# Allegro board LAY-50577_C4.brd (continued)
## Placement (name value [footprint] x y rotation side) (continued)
U5  UM1750S-00  [SOT23-5_A]  138.54 93.68 180 top
U6  MIMXRT1189CVM8C  [BGA289_0P8_14X14_1P52MM]  100.69 70.44 0 top
U10  W25Q128JWSIQ  [SO8-25X75-200]  149.59 65.86 90 bottom
U11  MT35XU512ABA2G12-0AAT  [PBGA24_1_6X8MM]  105.52 113.24 90 top
U12  W25Q128JWSIQ  [SO8-25X75-200]  105.91 122.51 270 bottom
U13  MX25L4006EM2R-12G  [SO8-25X75-200]  74.28 92.41 270 top
U14  W9825G6KH  [TSOPII_54]  60.05 77.68 270 top
U15  W956A8MBYA5K  [PBGA24_1_6X8MM]  83.42 83.01 270 top
U16  W9825G6KH  [TSOPII_54]  60.05 53.67 270 top
U22  NC7WV04L6X  [MICROPAK_6P]  132.06 21.16 90 top
U23  NL17SZ126DF  [SC-70]  145.52 20.65 270 top
U25  SRV05-4  [SOT23_S6]  52.3 21.12 0 bottom
U26  IP4292CZ10-TBR  [XSON10_0P5_1P1X2P6MM]  128.25 119.46 270 top
U27  RTL8211FDI-CG  [QFN40_0P4_5X5MM]  126.6 112.85 270 top
U28  IP4292CZ10-TBR  [XSON10_0P5_1P1X2P6MM]  124.44 119.46 270 top
U29  RTL8211FDI-CG  [QFN40_0P4_5X5MM]  26.9 59.13 0 top
U30  IP4292CZ10-TBR  [XSON10_0P5_1P1X2P6MM]  20.3 60.78 0 top
U31  IP4292CZ10-TBR  [XSON10_0P5_1P1X2P6MM]  20.3 56.97 0 top
U32  IP4292CZ10-TBR  [XSON10_0P5_1P1X2P6MM]  22.33 86.06 0 top
U33  IP4292CZ10-TBR  [XSON10_0P5_1P1X2P6MM]  22.33 82.25 0 top
U34  RTL8211FDI-CG  [QFN40_0P4_5X5MM]  28.94 84.41 0 top
U37  NX5P3090UK  [WLCSP12_0P4_1P38X1P68MM_SMDP]  184.64 56.97 90 top
U38  RClamp0854P.TCT  [SLP1616P6]  187.05 61.8 90 top
U39  NX5P3090UK  [WLCSP12_0P4_1P38X1P68MM_SMDP]  187.56 73.36 90 top
U40  RClamp0854P.TCT  [SLP1616P6]  187.05 80.72 90 top
U41  TJA1057GT/3  [SO8_1P27_4X5]  73.26 101.12 0 top
U42  TJA1057GT/3  [SO8_1P27_4X5]  73.26 106.84 0 top
U43  74AVC8T245PW  [TSSOP24_65MM]  164.32 100.28 90 top
U44  74AVC8T245PW  [TSSOP24_65MM]  155.56 100.28 270 top
U45  AMC1106M05DWV  [SOIC8_1P27_7P6X5P95MM]  163.43 33.1 180 top
U46  LSM6DSOXTR  [LGA14_0P5_3X2P5]  169.02 22.43 270 top
U48  24LC32A  [TSSOP8]  161.02 22.94 90 top
U51  PRTR5V0U2X  [SOT143B]  8.11 116.16 270 top
U52  NX5P3090UK  [WLCSP12_0P4_1P38X1P68MM_SMDP]  11.49 99.52 270 top
U55  LPC55S69JEV98  [BGA98_0P5_7X7]  27.54 116.16 270 top
U56  74LVC1T45GW,125  [SOT-363_0P65_SMT]  31.86 98 0 top
U57  74LVC1T45GW,125  [SOT-363_0P65_SMT]  31.86 101.55 0 top
U58  SN74LVC2T45  [SSOP8_DCU]  41 107.9 270 top
U59  74LVC1T45GW,125  [SOT-363_0P65_SMT]  31.86 104.98 180 top
U60  NX3DV2567GU  [PQFN16_0P4_2P65X1P85]  42.53 97.49 180 top
U61  74AVC4TD245BQ  [DHVQFN16_0P5_3P6X2P6]  40.37 114.63 180 top
U62  XC6206P332PR  [SOT89_123_A]  12.68 109.17 0 top
U63  TMUX136MRSER  [UQFN10_0P5_2P05X1P55]  145.14 117.17 180 top
U64  TMUX136MRSER  [UQFN10_0P5_2P05X1P55]  148.95 117.17 180 top
U65  TMUX136MRSER  [UQFN10_0P5_2P05X1P55]  140.95 117.17 180 top
U66  TMUX136MRSER  [UQFN10_0P5_2P05X1P55]  144.89 72.72 90 top
U67  TMUX136MRSER  [UQFN10_0P5_2P05X1P55]  149.84 72.72 90 top
U68  TMUX136MRSER  [UQFN10_0P5_2P05X1P55]  154.79 72.72 90 top
U69  TMUX136MRSER  [UQFN10_0P5_2P05X1P55]  101.71 105.62 0 top
U70  TMUX136MRSER  [UQFN10_0P5_2P05X1P55]  110.98 105.62 0 top
U71  TMUX136MRSER  [UQFN10_0P5_2P05X1P55]  106.03 105.62 0 top
U72  FT232RQ  [QFN32_MC1320X]  53.83 126.95 180 top
U73  SN74LVC2G126  [SSOP8]  56.24 121.24 0 top
U74  RClamp0854P.TCT  [SLP1616P6]  53.52 132.67 180 top
U96  TMUX136MRSER  [UQFN10_0P5_2P05X1P55]  43.03 84.28 90 top
U97  TMUX136MRSER  [UQFN10_0P5_2P05X1P55]  43.03 80.6 90 top
U98  TMUX136MRSER  [UQFN10_0P5_2P05X1P55]  43.03 76.91 90 top
U99  TMUX136MRSER  [UQFN10_0P5_2P05X1P55]  43.03 73.23 90 top
U100  TMUX136MRSER  [UQFN10_0P5_2P05X1P55]  43.03 69.55 90 top
U101  TMUX136MRSER  [UQFN10_0P5_2P05X1P55]  43.03 65.86 90 top
U103  TMUX136MRSER  [UQFN10_0P5_2P05X1P55]  43.03 59.39 90 top
U106  TMUX136MRSER  [UQFN10_0P5_2P05X1P55]  43.03 55.45 90 top
U115  FXLS8974CFR3  [DFN_10_0P4_2X2]  60.31 92.66 180 top
U116  SPH0641LM4H-1  [MIC5_3P6X2P75MM]  155.13 51.94 0 bottom
U117  SPH0641LM4H-1  [MIC5_3P6X2P75MM]  190.63 88.22 0 bottom
U118  SPH0641LM4H-1  [MIC5_3P6X2P75MM]  119.63 88.22 0 bottom
U119  SPH0641LM4H-1  [MIC5_3P6X2P75MM]  155.13 124.5 0 bottom
U121  RTL8201FI-VC-CG  [QFN32_0P5_5X5_S142EP]  57.51 31.07 90 top
U123  RTL8201FI-VC-CG  [QFN32_0P5_5X5_S142EP]  89.26 31.07 90 top
U124  SRV05-4  [SOT23_S6]  75.16 21.12 0 bottom
U125  NTS0102  [TSSOP8_A]  115.04 106.63 270 top
U126  NTS0102  [TSSOP8_A]  63.86 104.73 90 top
U312  DMG1016V-7  [SOT-563_6P_0P5_SMT]  121.11 61.5 0 top
U356  UM803RS  [SOT-23]  102.34 38.94 180 top
U361  74LVC07APW  [TSSOP14]  36.05 40.46 0 top
U362  74LVC1G07GW-Q100  [SC70-5]  57.26 104.09 0 bottom
U365  74LVC1G07GW-Q100  [SC70-5]  53.45 104.09 0 bottom
U366  74LVC1G07GW-Q100  [SC70-5]  49.64 104.09 0 bottom
U369  WM8962BECSN/R  [BGA49_0P5_3P62X4]  89.26 118.7 90 top
U410  74LVC1G07GW-Q100  [SC70-5]  121.52 118.06 90 bottom
U416  74LVC1G07GW-Q100  [SC70-5]  130.03 104.73 90 bottom
U417  74LVC1G07GW-Q100  [SC70-5]  24.62 75.39 0 top
U418  74LVC1G07GW-Q100  [SC70-5]  39.1 87.45 270 top
X1  25MHz  [XTAL4_5P2X3P4MM_SM]  135.82 118.95 0 top
X2  25MHz  [XTAL4_5P2X3P4MM_SM]  24.87 68.79 0 top
X3  25MHz  [XTAL4_5P2X3P4MM_SM]  26.9 94.06 0 top
X4  25MHz  [XTAL4_5P2X3P4MM_SM]  47.22 27.51 270 top
X6  25MHz  [XTAL4_5P2X3P4MM_SM]  78.72 27.51 270 top
Y1  32.768KHZ  [XTAL2-3P2X1P5-SM]  103.99 54.31 0 top
Y2  24MHz  [XTL4_2P1X1P7MM_SM]  109.33 55.58 180 top
Y3  32.7680KHZ  [XTLOSC4_3P3X1P6_SM]  172.19 119.2 270 top
Y4  16 MHz  [XTLOSC4_2P6X2P1MM_SM]  19.79 118.21 270 top

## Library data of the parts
BH1 BH12 = MOUNT_HOLE
C1-C3 C5 C6 C8 C10-C15 C17-C36 C39 C42-C49 C51 C53-C58 C60 C62 C64-C66 C69-C71 C73-C93 C98-C126 C165 C167-C170 C180-C248 C263 C264 C267 C268 C270-C273 C275-C279 C281-C301 C303-C312 C317 C338 C346-C356 C358-C365 C370-C373 C385-C395 C397-C414 C431-C436 C452 C455 C462-C466 C468-C473 C475-C478 C481 C482 C509 C515 C516 C522-C528 C562 C563 C565 C567 C569 C571 C573 C577-C603 C887 C902 = CAP_NP
C4 C166 C274 C280 C326 = CAP_NP: tolerance: 20%
C7 C9 C59 C61 C63 C68 C72 C94 C479 C480 C507 C508 C510 C517-C521 C529 C530 C574-C576 C604 C903 C908-C910 = F1202
C37 C38 C95 C96 C176-C179 C323 C324 C511-C514 = CAP_NP: tolerance: 5%
D1 = ZDIODE
D2 D4 D5 D8 D9 D25-D27 D41-D43 = DIODE_SCHTKY
D3 D37 = LED_DUAL_SEP_RG
D6 D7 D23 D24 D29-D33 D35 D39 = LED
D10-D20 = DIODE_TVS
D21 D22 = DIODE_NUP2105L
D28 = BAV99DW
D46 TVS1 = DIODE_TVS_BIDIR
F1 = FUSE
FL1 FL2 = FILTER_4P
H1-H6 = SPACER
J1 J51 = CONN_HDR_4X2
J2 = PHONEJACK-3
J3-J7 J9 J10 J12 J14 J23 J25 J26 J46 J49 J77-J81 J88-J100 J102-J105 J135 JP2-JP7 = CONN_HDR_2X1
J8 = HDR-1X12
J11 J34 J35 J57-J59 J63 J65 J72 J73 J75 J76 = CONN_HDR_3X1
J15 = CON8_SDCARD_DETECT
J24 J27 = KLPX0848A
J28 J32 = RJ45_7499211121A
J29-J31 = RJ45_2 DUAL_LED_10P
J33 J53 J60 J68 = MICRO_USB_CONN_9PIN
J36 = CON_67_FEMALE_RA
J37 J44 J69 = CONN_HDR_10X2
J39 J45 = CONN_HDR_8X2
J41 J67 = CONN_HDR_6X2
J47 = CONN_HDR_12X2
J48 J56 = CONN_HDR_5X2
J50 = CONN_HDR_4X1
J62 J70 = CONN_HDR_8X1
J71 = QSE_014_DP
J101 = 3.5MM_AUDIO_JACK
J108 = CONN_HDR_5X1
J134 = QSH030
JP1 = JUMPER1x2
L1 = IND: tolerance: 30%
L2-L4 L6-L9 L22 L33 L34 L36-L38 = INDUCTOR_FERRITE
L5 L15 L18 L23 L25 = INDUCTOR
L16 L19 L21 = DLW43
L24 = BEAD
L29 = IND_FERRITE
P2 = MIC_POM
Q1 Q2 = FDMA530PZ
Q3 = PNP
Q4 = NMOS_2N7002BKW_3P
Q5 Q11 Q12 = 2SK3018
Q6 = MOSFET_P
Q7 Q8 Q19-Q21 Q23 = NPN
Q15 = NMOS_3P_A
R1 R2 R6 R7 R12-R25 R27 R28 R30-R45 R47 R51-R59 R62 R71 R74 R76 R79-R89 R92-R116 R118 R120 R122 R124-R144 R146 R148 R149 R186-R188 R224-R227 R257 R260 R264 R266 R280 R283-R285 R291-R293 R295 R297-R299 R303 R308 R312-R320 R331 R336 R338 R339 R341 R343 R344 R348 R350 R376 R381 R382 R396 R397 R404 R405 R428-R457 R464 R466-R468 R470 R472-R477 R479-R481 R492-R510 R517 R519-R521 R523-R532 R543-R545 R547-R552 R554-R563 R570 R572-R574 R576 R622 R623 R625 R626 R628-R634 R636-R638 R640-R644 R646 R647 R649-R653 R655 R656 R658-R661 R663 R664 R669 R675-R692 R694 R696 R697 R699 R701 R703 R705-R738 R746-R753 R755-R785 R798 R800 R801 R803-R806 R808 R809 R811 R814-R818 R829-R842 R844 R845 R848 R849 R851 R853 R854 R861-R887 R891-R893 R898-R904 R958 R964 R1018 R1021-R1036 R1038-R1049 R1051-R1059 R1061-R1069 R1071-R1073 R1076-R1081 R1083-R1090 R1094-R1097 R1099 R1100 R1102-R1109 R1112 R1113 R1116-R1119 R1170-R1181 R1190-R1192 R1231 R1232 R1236 R1271 R1273 R1274 R1279 R1280 R1282-R1288 R1304-R1307 R1312-R1316 R1319-R1328 R1330-R1334 R1338-R1340 R1342-R1344 R1900 R2090 R2098-R2104 R2113 R2134-R2161 R2166 R2168 R2169 R2579 R2584-R2587 R2592 R2593 R2596 R2597 R2615 R2635 R2639-R2644 R2694 R2697 = RES
R3-R5 R8-R11 R64 R65 R256 R259 R270 R287-R290 R294 R335 R375 R378 R408 R465 R518 R571 R624 R627 R635 R639 R648 R657 R662 R665 R821-R828 R846 R847 R850 R852 R897 R1074 R1075 R1091 R1093 R1281 R2107 R2109 R2111 R2684 R2696 = RES: tolerance: 5%
R26 R377 R379 R380 R391-R393 R395 R469 R522 R575 R666 R667 R1275-R1278 R2695 = RES: tolerance: 1%
R29 R117 R119 R121 R123 R258 R296 R668 R670-R674 R2594 R2595 R2603-R2614 R2620 = RES: signal model: RES_0402_CC_DISCRETE_0.45_MM_470-75394_0_0
R151-R185 R189-R196 R198 R200-R223 R228-R235 R238 R240 R242 R244 R246 R248 R250 R252 R327 R332 R333 R337 R959 R960 R1122 R1169 R1229 R1230 R1233-R1235 R1237-R1240 R1259-R1270 R1272 R1289-R1303 R1308-R1311 R1329 R2114-R2133 = RES: signal model: RES_0402_CC_DISCRETE_0.45_MM_47_0
R271-R277 R2576 R2616-R2619 = RES: signal model: RES_RC0402_25_DISCRETE_0.4_MM_470-82894_0_0
R458-R463 R511-R516 R564-R569 = RES: tolerance: 5%; signal model: RES_0402_CC_DISCRETE_0.45_MM__1_0
R812 R813 = RES: signal model: RES_0402_CC_DISCRETE_0.41MM_470-75634_33_33
SW1 = SW_DPDT_3
SW2-SW4 SW7 SW8 = EDGE_MOUNT_PB_SW_2
SW5 = SW_DIP4
SW6 = SW2P_SPST
T1 T2 = XFMR: room: SPDIF
TP1 TP2 TP7-TP18 TP24-TP26 TP41 TP53-TP66 TP77 TP78 TP94-TP101 TP1022-TP1031 TP1065-TP1071 = T POINT R: Tolerance: TOLERANCE; User Part Number: 510-75618
TP3-TP6 = TEST_POINT
TP42-TP44 = TESTLOOP
TP45-TP48 TP51 TP67-TP76 TP102 TP103 TP1055-TP1064 = TestLoop
TP50 = TEST POINT L
U1 = MP2144GJ_TSOT23_8P
U2 = UM805_4P
U3 U5 = UM1750S-00_5P
U4 = LM1117_FXD
U6 = RT1180-BGA289
U10 U12 = 25WP_8P
U11 = MT35X_TBGA24
U13 = MX25L6406EM2I_SOP8
U14 U16 = W9825G6KH_54P
U15 = W959D8NFYA5_TFBGA24
U22 = 74AUP2G06GW
U23 = 100201_SO-1
U25 U124 = SRV05-4
U26 U28 U30-U33 = PUSB3F96_DFN2510A_10P
U27 U29 U34 = RTL8211FD-40P
U37 U39 U52 = NX5P3090UK_WLCSP12
U38 U40 U74 = RCLAMP1654P_NEW
U41 U42 = TJA1057GT3_8P
U43 U44 = SN74AVC8T245
U45 = AMC1106_SOIC8P
U46 = LSM6DSO_LGA14P
U48 = Atmel_Serial_EEPROM_64K-1
U51 = PRTR5V0U2X: signal model: PRTR5V0U2X_SOT143B_IC_1.1MM_315_PRTR5V0U2X
U55 = NIOBE4_MINI_FBGA98
U56 U57 U59 = 74LVCH1T45_6P
U58 = SN74LVC2T45DCUT_8P
U60 = NX3DV2567GU_XQFN_16P
U61 = 74AVC4TD245BQ_DHVQFN16
U62 = S0T89_3P
U63-U71 U96-U101 U103 U106 = TMUX136_UQFN10
U72 = FT232RQ
U73 = SN74LVC2G126DCTR
U115 = FXLS8962AF_DFN10
U116-U119 = MIC_SPH0641LM4H-1_5P
U121 = RTL8201FI: signal model: RES_0402_CC_DISCRETE_0.45_MM_47_0
U123 = RTL8201FI
U125 U126 = NTB0102_8P
U312 = NX3008_SOT666_6PIN
U356 = SGM803_SOT23-3P
U361 = 74LVC07APW
U362 U365 U366 U410 U416-U418 = 74AUP1G07GW
U369 = WM8962_BGA_49P_CUST
X1-X4 X6 Y2 Y4 = XTAL_13
Y1 = CRYSTAL
Y3 = OSC_4P

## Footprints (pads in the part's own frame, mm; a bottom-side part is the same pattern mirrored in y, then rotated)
100MIL_TH
  rect 1.422x1.422 hole 0.914: 1(0,0)
  round 1.422 hole 0.914: 2(2.54,0)
0402_CC
  rect 0.457x0.508 smd: 1(-0.375,0) 2(0.375,0)
BGA49_0P5_3P62X4
  round 0.254 smd: A1(-1.5,1.5) A2(-1,1.5) A3(-0.5,1.5) A4(0,1.5) A5(0.5,1.5) A6(1,1.5) A7(1.5,1.5) B1(-1.5,1) B2(-1,1) B3(-0.5,1) B4(0,1) B5(0.5,1) B6(1,1) B7(1.5,1) C1(-1.5,0.5) C2(-1,0.5) C3(-0.5,0.5) C4(0,0.5) C5(0.5,0.5) C6(1,0.5) C7(1.5,0.5) D1(-1.5,0) D2(-1,0) D3(-0.5,0) D4(0,0) D5(0.5,0) D6(1,0) D7(1.5,0) E1(-1.5,-0.5) E2(-1,-0.5) E3(-0.5,-0.5) E4(0,-0.5) E5(0.5,-0.5) E6(1,-0.5) E7(1.5,-0.5) F1(-1.5,-1) F2(-1,-1) F3(-0.5,-1) F4(0,-1) F5(0.5,-1) F6(1,-1) F7(1.5,-1) G1(-1.5,-1.5) G2(-1,-1.5) G3(-0.5,-1.5) G4(0,-1.5) G5(0.5,-1.5) G6(1,-1.5) G7(1.5,-1.5)
BGA98_0P5_7X7
  round 0.279 smd: A1(-3,3) A2(-2.5,3) A3(-2,3) A5(-1,3) A6(-0.5,3) A7(0,3) A8(0.5,3) A9(1,3) A11(2,3) A12(2.5,3) A13(3,3) B1(-3,2.5) B2(-2.5,2.5) B3(-2,2.5) B5(-1,2.5) B6(-0.5,2.5) B7(0,2.5) B8(0.5,2.5) B9(1,2.5) B11(2,2.5) B12(2.5,2.5) B13(3,2.5) C1(-3,2) C2(-2.5,2) C7(0,2) C12(2.5,2) C13(3,2) E1(-3,1) E2(-2.5,1) E5(-1,1) E6(-0.5,1) E7(0,1) E8(0.5,1) E9(1,1) E12(2.5,1) E13(3,1) F1(-3,0.5) F2(-2.5,0.5) F5(-1,0.5) F6(-0.5,0.5) F8(0.5,0.5) F9(1,0.5) F12(2.5,0.5) F13(3,0.5) G1(-3,0) G2(-2.5,0) G3(-2,0) G5(-1,0) G6(-0.5,0) G8(0.5,0) G9(1,0) G11(2,0) G12(2.5,0) G13(3,0) H1(-3,-0.5) H2(-2.5,-0.5) H5(-1,-0.5) H6(-0.5,-0.5) H8(0.5,-0.5) H9(1,-0.5) H12(2.5,-0.5) H13(3,-0.5) J1(-3,-1) J2(-2.5,-1) J5(-1,-1) J6(-0.5,-1) J7(0,-1) J8(0.5,-1) J9(1,-1) J12(2.5,-1) J13(3,-1) L1(-3,-2) L2(-2.5,-2) L7(0,-2) L12(2.5,-2) L13(3,-2) M1(-3,-2.5) M2(-2.5,-2.5) M3(-2,-2.5) M5(-1,-2.5) M6(-0.5,-2.5) M7(0,-2.5) M8(0.5,-2.5) M9(1,-2.5) M11(2,-2.5) M12(2.5,-2.5) M13(3,-2.5) N1(-3,-3) N2(-2.5,-3) N3(-2,-3) N5(-1,-3) N6(-0.5,-3) N7(0,-3) N8(0.5,-3) N9(1,-3) N11(2,-3) N12(2.5,-3) N13(3,-3)
BGA289_0P8_14X14_1P52MM
  round 0.33 smd: A1(-6.4,6.4) A2(-5.6,6.4) A3(-4.8,6.4) A4(-4,6.4) A5(-3.2,6.4) A6(-2.4,6.4) A7(-1.6,6.4) A8(-0.8,6.4) A9(0,6.4) A10(0.8,6.4) A11(1.6,6.4) A12(2.4,6.4) A13(3.2,6.4) A14(4,6.4) A15(4.8,6.4) A16(5.6,6.4) A17(6.4,6.4) B1(-6.4,5.6) B2(-5.6,5.6) B3(-4.8,5.6) B4(-4,5.6) B5(-3.2,5.6) B6(-2.4,5.6) B7(-1.6,5.6) B8(-0.8,5.6) B9(0,5.6) B10(0.8,5.6) B11(1.6,5.6) B12(2.4,5.6) B13(3.2,5.6) B14(4,5.6) B15(4.8,5.6) B16(5.6,5.6) B17(6.4,5.6) C1(-6.4,4.8) C2(-5.6,4.8) C3(-4.8,4.8) C4(-4,4.8) C5(-3.2,4.8) C6(-2.4,4.8) C7(-1.6,4.8) C8(-0.8,4.8) C9(0,4.8) C10(0.8,4.8) C11(1.6,4.8) C12(2.4,4.8) C13(3.2,4.8) C14(4,4.8) C15(4.8,4.8) C16(5.6,4.8) C17(6.4,4.8) D1(-6.4,4) D2(-5.6,4) D3(-4.8,4) D4(-4,4) D5(-3.2,4) D6(-2.4,4) D7(-1.6,4) D8(-0.8,4) D9(0,4) D10(0.8,4) D11(1.6,4) D12(2.4,4) D13(3.2,4) D14(4,4) D15(4.8,4) D16(5.6,4) D17(6.4,4) E1(-6.4,3.2) E2(-5.6,3.2) E3(-4.8,3.2) E4(-4,3.2) E5(-3.2,3.2) E6(-2.4,3.2) E7(-1.6,3.2) E8(-0.8,3.2) E9(0,3.2) E10(0.8,3.2) E11(1.6,3.2) E12(2.4,3.2) E13(3.2,3.2) E14(4,3.2) E15(4.8,3.2) E16(5.6,3.2) E17(6.4,3.2) F1(-6.4,2.4) F2(-5.6,2.4) F3(-4.8,2.4) F4(-4,2.4) F5(-3.2,2.4) F6(-2.4,2.4) F7(-1.6,2.4) F8(-0.8,2.4) F9(0,2.4) F10(0.8,2.4) F11(1.6,2.4) F12(2.4,2.4) F13(3.2,2.4) F14(4,2.4) F15(4.8,2.4) F16(5.6,2.4) F17(6.4,2.4) G1(-6.4,1.6) G2(-5.6,1.6) G3(-4.8,1.6) G4(-4,1.6) G5(-3.2,1.6) G6(-2.4,1.6) G7(-1.6,1.6) G8(-0.8,1.6) G9(0,1.6) G10(0.8,1.6) G11(1.6,1.6) G12(2.4,1.6) G13(3.2,1.6) G14(4,1.6) G15(4.8,1.6) G16(5.6,1.6) G17(6.4,1.6) H1(-6.4,0.8) H2(-5.6,0.8) H3(-4.8,0.8) H4(-4,0.8) H5(-3.2,0.8) H6(-2.4,0.8) H7(-1.6,0.8) H8(-0.8,0.8) H9(0,0.8) H10(0.8,0.8) H11(1.6,0.8) H12(2.4,0.8) H13(3.2,0.8) H14(4,0.8) H15(4.8,0.8) H16(5.6,0.8) H17(6.4,0.8) J1(-6.4,0) J2(-5.6,0) J3(-4.8,0) J4(-4,0) J5(-3.2,0) J6(-2.4,0) J7(-1.6,0) J8(-0.8,0) J9(0,0) J10(0.8,0) J11(1.6,0) J12(2.4,0) J13(3.2,0) J14(4,0) J15(4.8,0) J16(5.6,0) J17(6.4,0) K1(-6.4,-0.8) K2(-5.6,-0.8) K3(-4.8,-0.8) K4(-4,-0.8) K5(-3.2,-0.8) K6(-2.4,-0.8) K7(-1.6,-0.8) K8(-0.8,-0.8) K9(0,-0.8) K10(0.8,-0.8) K11(1.6,-0.8) K12(2.4,-0.8) K13(3.2,-0.8) K14(4,-0.8) K15(4.8,-0.8) K16(5.6,-0.8) K17(6.4,-0.8) L1(-6.4,-1.6) L2(-5.6,-1.6) L3(-4.8,-1.6) L4(-4,-1.6) L5(-3.2,-1.6) L6(-2.4,-1.6) L7(-1.6,-1.6) L8(-0.8,-1.6) L9(0,-1.6) L10(0.8,-1.6) L11(1.6,-1.6) L12(2.4,-1.6) L13(3.2,-1.6) L14(4,-1.6) L15(4.8,-1.6) L16(5.6,-1.6) L17(6.4,-1.6) M1(-6.4,-2.4) M2(-5.6,-2.4) M3(-4.8,-2.4) M4(-4,-2.4) M5(-3.2,-2.4) M6(-2.4,-2.4) M7(-1.6,-2.4) M8(-0.8,-2.4) M9(0,-2.4) M10(0.8,-2.4) M11(1.6,-2.4) M12(2.4,-2.4) M13(3.2,-2.4) M14(4,-2.4) M15(4.8,-2.4) M16(5.6,-2.4) M17(6.4,-2.4) N1(-6.4,-3.2) N2(-5.6,-3.2) N3(-4.8,-3.2) N4(-4,-3.2) N5(-3.2,-3.2) N6(-2.4,-3.2) N7(-1.6,-3.2) N8(-0.8,-3.2) N9(0,-3.2) N10(0.8,-3.2) N11(1.6,-3.2) N12(2.4,-3.2) N13(3.2,-3.2) N14(4,-3.2) N15(4.8,-3.2) N16(5.6,-3.2) N17(6.4,-3.2) P1(-6.4,-4) P2(-5.6,-4) P3(-4.8,-4) P4(-4,-4) P5(-3.2,-4) P6(-2.4,-4) P7(-1.6,-4) P8(-0.8,-4) P9(0,-4) P10(0.8,-4) P11(1.6,-4) P12(2.4,-4) P13(3.2,-4) P14(4,-4) P15(4.8,-4) P16(5.6,-4) P17(6.4,-4) R1(-6.4,-4.8) R2(-5.6,-4.8) R3(-4.8,-4.8) R4(-4,-4.8) R5(-3.2,-4.8) R6(-2.4,-4.8) R7(-1.6,-4.8) R8(-0.8,-4.8) R9(0,-4.8) R10(0.8,-4.8) R11(1.6,-4.8) R12(2.4,-4.8) R13(3.2,-4.8) R14(4,-4.8) R15(4.8,-4.8) R16(5.6,-4.8) R17(6.4,-4.8) T1(-6.4,-5.6) T2(-5.6,-5.6) T3(-4.8,-5.6) T4(-4,-5.6) T5(-3.2,-5.6) T6(-2.4,-5.6) T7(-1.6,-5.6) T8(-0.8,-5.6) T9(0,-5.6) T10(0.8,-5.6) T11(1.6,-5.6) T12(2.4,-5.6) T13(3.2,-5.6) T14(4,-5.6) T15(4.8,-5.6) T16(5.6,-5.6) T17(6.4,-5.6) U1(-6.4,-6.4) U2(-5.6,-6.4) U3(-4.8,-6.4) U4(-4,-6.4) U5(-3.2,-6.4) U6(-2.4,-6.4) U7(-1.6,-6.4) U8(-0.8,-6.4) U9(0,-6.4) U10(0.8,-6.4) U11(1.6,-6.4) U12(2.4,-6.4) U13(3.2,-6.4) U14(4,-6.4) U15(4.8,-6.4) U16(5.6,-6.4) U17(6.4,-6.4)
CC0402_25
  round 0.635 smd: 1(-0.508,0) 2(0.508,0)
CC0402_TOL0P2
  rect 0.457x0.61 smd: 1(-0.475,0) 2(0.475,0)
CC0402_TOL0P15
  rect 0.457x0.61 smd: 1(-0.475,0) 2(0.475,0)
CC0603_OV
  oval 0.889x1.143 smd: 1(-0.762,0) 2(0.762,0)
CC1206
  rect 1.6x1.6 smd: 1(-1.753,0) 2(1.753,0)
CC1206_OV
  oval 1.016x1.778 smd: 1(-1.524,0) 2(1.524,0)
CON2_RCA_RA_TH
  oval 2x3.65 hole 1.2x2.2: 1(0,0)
  oval 3.302x1.651 hole 2.007x1.016: 2(4.5,0)
CON2X5_50_TH_A
  rect 1.092x1.092 hole 0.711: 1(0,0)
  round 1.092 hole 0.711: 2(0,1.27) 3(1.27,0) 4(1.27,1.27) 5(2.54,0) 6(2.54,1.27) 7(3.81,0) 8(3.81,1.27) 9(5.08,0) 10(5.08,1.27)
CON3_PWR_TH
  oval 4.013x1.549 hole 3.5x0.8: 1(0,0)
  oval 3.759x1.549 hole 2.997x0.787: 2(0,-6)
  oval 1.549x3.759 hole 0.787x2.997: 3(4.8,-2.5)
CON5_AUD_JACK_RA_TH_SJ-43514
  round 0.254 hole 1.092 unplated: (-8.1,-1.6) (-3.1,-1.6)
  rect 1.702x1.702 hole 1.092: 1(0,0)
  round 1.702 hole 1.092: 4(-3.1,-5.2) 5(-8.1,3.2) 6(-8.1,-6.1)
CON9_MICROAB_USB_SHELL_TH
  rect 1.803x1.905 smd: (-1.15,0) (1.15,0)
  rect 0.406x1.346 smd: 1(-1.3,2.8) 2(-0.65,2.8) 3(0,2.8) 4(0.65,2.8) 5(1.3,2.8)
  oval 1.067x1.27 hole 0.66x0.864: 6(2.225,3.125) 9(-2.225,3.125)
  rect 2.21x1.905 hole 1.499x0.838: 7(4.175,0) 8(-4.175,0)
CON_1X8_SKT_2P54_TH
  rect 1.702x1.702 hole 1.016: 1(0,0)
  round 1.702 hole 1.016: 2(0,-2.54) 3(0,-5.08) 4(0,-7.62) 5(0,-10.16) 6(0,-12.7) 7(0,-15.24) 8(0,-17.78)
CON_2X4_SKT_100_SM
  rect 2.235x1.016 smd: 1(2.826,3.81) 2(-2.826,3.81) 3(2.826,1.27) 4(-2.826,1.27) 5(2.826,-1.27) 6(-2.826,-1.27) 7(2.826,-3.81) 8(-2.826,-3.81)
CON_2X8_SKT_100_TH
  rect 1.651x1.651 hole 1.016: 1(0,0)
  round 1.651 hole 1.016: 2(0,-2.54) 3(2.54,0) 4(2.54,-2.54) 5(5.08,0) 6(5.08,-2.54) 7(7.62,0) 8(7.62,-2.54) 9(10.16,0) 10(10.16,-2.54) 11(12.7,0) 12(12.7,-2.54) 13(15.24,0) 14(15.24,-2.54) 15(17.78,0) 16(17.78,-2.54)
CON_014_QSE_DP_F
  round 0 hole 1.016 unplated: (-10.066,2.667) (10.064,2.667)
  rect 0.406x2.286 smd: 1(-7.601,-2.87) 2(-7.601,2.87) 3(-6.801,-2.87) 4(-6.801,2.87) 5(-5.201,-2.87) 6(-5.201,2.87) 7(-4.401,-2.87) 8(-4.401,2.87) 9(-2.801,-2.87) 10(-2.801,2.87) 11(-2.001,-2.87) 12(-2.001,2.87) 13(-0.401,-2.87) 14(-0.401,2.87) 15(0.399,-2.87) 16(0.399,2.87) 17(1.999,-2.87) 18(1.999,2.87) 19(2.799,-2.87) 20(2.799,2.87) 21(4.399,-2.87) 22(4.399,2.87) 23(5.199,-2.87) 24(5.199,2.87) 25(6.799,-2.87) 26(6.799,2.87) 27(7.599,-2.87) 28(7.599,2.87)
  rect 2.54x0.432 smd: SH1(-8.065,0) SH4(8.065,0)
  rect 4.699x0.432 smd: SH2(-3.175,0) SH3(3.175,0)
CON_60S_QSH_SM_A
  round 0 hole 1.016 unplated: (-10.067,2.667) (10.067,2.667)
  rect 0.279x2.286 smd: 1(-7.256,-2.865) 2(-7.256,2.865) 3(-6.755,-2.865) 4(-6.755,2.865) 5(-6.255,-2.865) 6(-6.255,2.865) 7(-5.754,-2.865) 8(-5.754,2.865) 9(-5.254,-2.865) 10(-5.254,2.865) 11(-4.754,-2.865) 12(-4.754,2.865) 13(-4.253,-2.865) 14(-4.253,2.865) 15(-3.753,-2.865) 16(-3.753,2.865) 17(-3.252,-2.865) 18(-3.252,2.865) 19(-2.752,-2.865) 20(-2.752,2.865) 21(-2.252,-2.865) 22(-2.252,2.865) 23(-1.751,-2.865) 24(-1.751,2.865) 25(-1.251,-2.865) 26(-1.251,2.865) 27(-0.751,-2.865) 28(-0.751,2.865) 29(-0.25,-2.865) 30(-0.25,2.865) 31(0.25,-2.865) 32(0.25,2.865) 33(0.751,-2.865) 34(0.751,2.865) 35(1.251,-2.865) 36(1.251,2.865) 37(1.751,-2.865) 38(1.751,2.865) 39(2.252,-2.865) 40(2.252,2.865) 41(2.752,-2.865) 42(2.752,2.865) 43(3.252,-2.865) 44(3.252,2.865) 45(3.753,-2.865) 46(3.753,2.865) 47(4.253,-2.865) 48(4.253,2.865) 49(4.754,-2.865) 50(4.754,2.865) 51(5.254,-2.865) 52(5.254,2.865) 53(5.754,-2.865) 54(5.754,2.865) 55(6.255,-2.865) 56(6.255,2.865) 57(6.755,-2.865) 58(6.755,2.865) 59(7.256,-2.865) 60(7.256,2.865)
  rect 2.54x0.432 smd: SH1(-8.065,0) SH4(8.065,0)
  rect 4.699x0.432 smd: SH2(-3.175,0) SH3(3.175,0)
CON_67_0P5_22X7P75_RA
  rect 1.194x2.743 smd: (-10.35,3.125) (10.35,3.125)
  round 0.254 hole 1.092 unplated: (-10,-1.375)
  round 0.254 hole 1.6 unplated: (10,-1.375)
  rect 0.305x1.549 smd: 1(-9.25,3.9) 2(-9,-3.65) 3(-8.75,3.9) 4(-8.5,-3.65) 5(-8.25,3.9) 6(-8,-3.65) 7(-7.75,3.9) 8(-7.5,-3.65) 9(-7.25,3.9) 10(-7,-3.65) 11(-6.75,3.9) 12(-6.5,-3.65) 13(-6.25,3.9) 14(-6,-3.65) 15(-5.75,3.9) 16(-5.5,-3.65) 17(-5.25,3.9) 18(-5,-3.65) 19(-4.75,3.9) 20(-4.5,-3.65) 21(-4.25,3.9) 22(-4,-3.65) 23(-3.75,3.9) 32(-1.5,-3.65) 33(-1.25,3.9) 34(-1,-3.65) 35(-0.75,3.9) 36(-0.5,-3.65) 37(-0.25,3.9) 38(0,-3.65) 39(0.25,3.9) 40(0.5,-3.65) 41(0.75,3.9) 42(1,-3.65) 43(1.25,3.9) 44(1.5,-3.65) 45(1.75,3.9) 46(2,-3.65) 47(2.25,3.9) 48(2.5,-3.65) 49(2.75,3.9) 50(3,-3.65) 51(3.25,3.9) 52(3.5,-3.65) 53(3.75,3.9) 54(4,-3.65) 55(4.25,3.9) 56(4.5,-3.65) 57(4.75,3.9) 58(5,-3.65) 59(5.25,3.9) 60(5.5,-3.65) 61(5.75,3.9) 62(6,-3.65) 63(6.25,3.9) 64(6.5,-3.65) 65(6.75,3.9) 66(7,-3.65) 67(7.25,3.9) 68(7.5,-3.65) 69(7.75,3.9) 70(8,-3.65) 71(8.25,3.9) 72(8.5,-3.65) 73(8.75,3.9) 74(9,-3.65) 75(9.25,3.9)
CON_RJ45_2LED_TH_A
  round 0.254 hole 3.251 unplated: (-11.43,8.89) (0,8.89)
  rect 1.499x1.499 hole 0.889: 1(0,0)
  round 1.499 hole 0.889: 2(-1.27,2.54) 3(-2.54,0) 4(-3.81,2.54) 5(-5.08,0) 6(-6.35,2.54) 7(-7.62,0) 8(-8.89,2.54) 9(-10.16,0) 10(-11.43,2.54)
  round 1.651 hole 1.016: 11(0.914,12.97) 12(-1.626,12.97) 13(-9.804,12.97) 14(-12.344,12.97)
  round 2.642 hole 1.6: 15(2.03,5.842) 16(-13.46,5.842)
CON_RJ45_10_2LED_TH
  round 0.254 hole 3.251 unplated: (-11.43,8.89) (0,8.89)
  rect 1.499x1.499 hole 0.889: 1(0,0)
  round 1.499 hole 0.889: 2(-1.27,2.54) 3(-2.54,0) 4(-3.81,2.54) 5(-5.08,0) 6(-6.35,2.54) 7(-7.62,0) 8(-8.89,2.54) 9(-10.16,0) 10(-11.43,2.54)
  round 1.651 hole 1.016: 11(0.915,12.97) 12(-1.625,12.97) 13(-9.805,12.97) 14(-12.345,12.97)
  round 2.642 hole 1.6: SH1(2.03,5.84) SH2(-13.46,5.84)
CON_SDCARD_95220
  rect 0.813x1.499 smd: 1(-1.94,3.267) 2(-0.84,2.867) 3(0.26,3.267) 4(1.36,3.468) 5(2.46,3.267) 6(3.56,3.468) 7(4.66,3.267) 8(5.76,3.267)
  rect 0.991x0.94 smd: 9(3.56,-7.368)
  rect 1.397x1.905 smd: SH1(6.6,6.187) SH2(-6.6,7.107)
  rect 1.295x1.422 smd: SH3(4.95,-7.092) SH4(-0.75,-7.092)
CON_SKT2X6_TH
  rect 1.676x1.676 hole 1.041: 1(0,0)
  round 1.676 hole 1.041: 2(0,2.54) 3(-2.54,0) 4(-2.54,2.54) 5(-5.08,0) 6(-5.08,2.54) 7(-7.62,0) 8(-7.62,2.54) 9(-10.16,0) 10(-10.16,2.54) 11(-12.7,0) 12(-12.7,2.54)
CON_SKT2X10_TH
  rect 1.651x1.651 hole 1.016: 1(0,0)
  round 1.651 hole 1.016: 2(-2.54,0) 3(0,-2.54) 4(-2.54,-2.54) 5(0,-5.08) 6(-2.54,-5.08) 7(0,-7.62) 8(-2.54,-7.62) 9(0,-10.16) 10(-2.54,-10.16) 11(0,-12.7) 12(-2.54,-12.7) 13(0,-15.24) 14(-2.54,-15.24) 15(0,-17.78) 16(-2.54,-17.78) 17(0,-20.32) 18(-2.54,-20.32) 19(0,-22.86) 20(-2.54,-22.86)
DFN2_0P65_1P05X0P65MM
  rect 0.356x0.61 smd: 1(-0.325,0) 2(0.325,0)
DFN_10_0P4_2X2
  rect 0.787x0.229 smd: 1(-0.925,0.8) 2(-0.925,0.4) 3(-0.925,0) 4(-0.925,-0.4) 5(-0.925,-0.8) 6(0.925,-0.8) 7(0.925,-0.4) 8(0.925,0) 9(0.925,0.4) 10(0.925,0.8)
DHVQFN16_0P5_3P6X2P6
  rect 0.305x0.838 smd: 1(-0.25,1.719) 8(-0.25,-1.719) 9(0.25,-1.719) 16(0.25,1.719)
  rect 0.838x0.305 smd: 2(-1.219,1.25) 3(-1.219,0.75) 4(-1.219,0.25) 5(-1.219,-0.25) 6(-1.219,-0.75) 7(-1.219,-1.25) 10(1.219,-1.25) 11(1.219,-0.75) 12(1.219,-0.25) 13(1.219,0.25) 14(1.219,0.75) 15(1.219,1.25)
  rect 1.143x2.159 smd: 17(0,0)
DIODE2_SOD523
  rect 0.61x0.813 smd: 1(-0.85,0) 2(0.85,0)
F204
  rect 0.457x0.508 smd: 1(-0.375,0) 2(0.375,0)
FUSE_3P4X1P8
  rect 0.991x1.803 smd: 1(-1.25,0) 2(1.25,0)
HDR1X2_50MIL
  rect 1.092x1.092 hole 0.711: 1(0,0)
  round 1.092 hole 0.711: 2(0,-1.27)
HDR2X4_2P54_TH
  rect 1.6x1.6 hole 1.092: 1(0,0)
  round 1.6 hole 1.092: 2(2.54,0) 3(0,-2.54) 4(2.54,-2.54) 5(0,-5.08) 6(2.54,-5.08) 7(0,-7.62) 8(2.54,-7.62)
HDR2X5_2MM_TH
  rect 1.346x1.346 hole 0.838: 1(0,0)
  round 1.346 hole 0.838: 2(0,2) 3(2,0) 4(2,2) 5(4,0) 6(4,2) 7(6,0) 8(6,2) 9(8,0) 10(8,2)
HDR2X6_2P54_TH
  rect 1.6x1.6 hole 1.092: 1(0,0)
  round 1.6 hole 1.092: 2(2.54,0) 3(0,-2.54) 4(2.54,-2.54) 5(0,-5.08) 6(2.54,-5.08) 7(0,-7.62) 8(2.54,-7.62) 9(0,-10.16) 10(2.54,-10.16) 11(0,-12.7) 12(2.54,-12.7)
HDR2X12_2MM_TH
  rect 1.346x1.346 hole 0.838: 1(0,0)
  round 1.346 hole 0.838: 2(0,2) 3(2,0) 4(2,2) 5(4,0) 6(4,2) 7(6,0) 8(6,2) 9(8,0) 10(8,2) 11(10,0) 12(10,2) 13(12,0) 14(12,2) 15(14,0) 16(14,2) 17(16,0) 18(16,2) 19(18,0) 20(18,2) 21(20,0) 22(20,2) 23(22,0) 24(22,2)
HDR102
  rect 1.524x1.524 hole 1.016: 1(0,0)
  round 1.524 hole 1.016: 2(0,-2.54)
HDR103
  rect 1.524x1.524 hole 1.016: 1(0,0)
  round 1.524 hole 1.016: 2(0,-2.54) 3(0,-5.08)
HDR104_STAG_TSM_SM
  rect 3.175x1.27 smd: 1(1.6,3.81) 2(-1.6,1.27) 3(1.6,-1.27) 4(-1.6,-3.81)
HDR105
  rect 1.676x1.676 hole 1.016: 1(0,0)
  round 1.676 hole 1.016: 2(0,-2.54) 3(0,-5.08) 4(0,-7.62) 5(0,-10.16)
HDR112_B
  rect 1.6x1.6 hole 1.092: 1(0,0)
  round 1.6 hole 1.092: 2(0,-2.54) 3(0,-5.08) 4(0,-7.62) 5(0,-10.16) 6(0,-12.7) 7(0,-15.24) 8(0,-17.78) 9(0,-20.32) 10(0,-22.86) 11(0,-25.4) 12(0,-27.94)
HDR210_344H
  rect 1.676x1.676 hole 1.016: 1(0,0)
  round 1.676 hole 1.016: 2(2.54,0) 3(0,-2.54) 4(2.54,-2.54) 5(0,-5.08) 6(2.54,-5.08) 7(0,-7.62) 8(2.54,-7.62) 9(0,-10.16) 10(2.54,-10.16) 11(0,-12.7) 12(2.54,-12.7) 13(0,-15.24) 14(2.54,-15.24) 15(0,-17.78) 16(2.54,-17.78) 17(0,-20.32) 18(2.54,-20.32) 19(0,-22.86) 20(2.54,-22.86)
HDR_2X10M_100_TH
  rect 1.778x1.778 hole 1.143: 1(0,0)
  round 1.778 hole 1.143: 2(2.54,0) 3(0,-2.54) 4(2.54,-2.54) 5(0,-5.08) 6(2.54,-5.08) 7(0,-7.62) 8(2.54,-7.62) 9(0,-10.16) 10(2.54,-10.16) 11(0,-12.7) 12(2.54,-12.7) 13(0,-15.24) 14(2.54,-15.24) 15(0,-17.78) 16(2.54,-17.78) 17(0,-20.32) 18(2.54,-20.32) 19(0,-22.86) 20(2.54,-22.86)
IND4_4P7X3P4_SMT
  rect 1.372x0.914 smd: 1(-2.275,1.25) 2(-2.275,-1.25) 3(2.275,-1.25) 4(2.275,1.25)
IND4_CHOKE_0805
  rect 0.914x0.406 smd: 1(-0.85,-0.4) 2(0.85,-0.4) 3(0.85,0.4) 4(-0.85,0.4)
IND_1P8X1MM_SM
  rect 0.991x0.711 smd: 1(-0.845,0) 2(0.845,0)
IND_4P2X4P2
  rect 1.499x3.607 smd: 1(-1.525,0) 2(1.525,0)
IND_0402
  round 0.635 smd: 1(-0.508,0) 2(0.508,0)
IND_0603
  rect 0.991x0.813 smd: 1(-0.69,0) 2(0.69,0)
IND_0805
  rect 1.295x1.499 smd: 1(-0.978,0) 2(0.978,0)
IND_4020
  rect 1.118x3.708 smd: 1(-1.5,0) 2(1.5,0)
LED_0603
  rect 0.838x0.787 smd: A(-0.775,0) C(0.775,0)
LED_DUAL_3025MM_SM
  rect 1.702x1.118 smd: 1(-1.35,-0.85) 2(1.35,-0.85) 3(-1.35,0.85) 4(1.35,0.85)
LGA14_0P5_3X2P5
  rect 0.457x0.254 smd: 1(-1.175,0.75) 2(-1.175,0.25) 3(-1.175,-0.25) 4(-1.175,-0.75) 8(1.175,-0.75) 9(1.175,-0.25) 10(1.175,0.25) 11(1.175,0.75)
  rect 0.254x0.457 smd: 5(-0.5,-0.925) 6(0,-0.925) 7(0.5,-0.925) 12(0.5,0.925) 13(0,0.925) 14(-0.5,0.925)
MH244-166T
  round 6.198 hole 4.216: 1(0,0)
MH256P130
  round 6.502 hole 3.302: 1(0,0)
MIC5_3P6X2P75MM
  round 0 hole 0.381 unplated: (0,-0.71)
  rect 0.711x0.508 smd: 1(-0.831,1.364) 2(-0.831,0.542) 4(0.831,0.542) 5(0.831,1.364)
  round 0 smd: 3(-0.66,-0.71)
MIC_WM-63PR
  rect 1.27x1.27 hole 0.762: 1(0,0)
  round 1.27 hole 0.762: 2(0,1.9)
MICROPAK_6P
  rect 0.305x0.508 smd: 1(-0.508,-0.381) 2(0,-0.381) 3(0.508,-0.381) 4(0.508,0.381) 5(0,0.381) 6(-0.508,0.381)
MLP6_2X2MM_SLUG
  rect 0.483x0.406 smd: 1(-0.913,0.65) 2(-0.913,0) 3(-0.913,-0.65) 4(0.913,-0.65) 5(0.913,0) 6(0.913,0.65)
  rect 1.016x0.991 smd: 7(0,0.3)
  rect 0.66x0.406 smd: 8(0,-0.65)
PBGA24_1_6X8MM
  round 0.33 smd: A2(-1,2) A3(0,2) A4(1,2) A5(2,2) B1(-2,1) B2(-1,1) B3(0,1) B4(1,1) B5(2,1) C1(-2,0) C2(-1,0) C3(0,0) C4(1,0) C5(2,0) D1(-2,-1) D2(-1,-1) D3(0,-1) D4(1,-1) D5(2,-1) E1(-2,-2) E2(-1,-2) E3(0,-2) E4(1,-2) E5(2,-2)
PQFN16_0P4_2P65X1P85
  rect 0.203x0.762 smd: 1(-0.6,-0.724)
  rect 0.203x0.66 smd: 2(-0.2,-0.775) 3(0.2,-0.775) 4(0.6,-0.775) 9(0.6,0.775) 10(0.2,0.775) 11(-0.2,0.775) 12(-0.6,0.775)
  rect 0.66x0.203 smd: 5(1.21,-0.6) 6(1.21,-0.2) 7(1.21,0.2) 8(1.21,0.6) 13(-1.21,0.6) 14(-1.21,0.2) 15(-1.21,-0.2) 16(-1.21,-0.6)
QFN32_0P5_5X5_S142EP
  oval 0.813x0.305 smd: 1(-2.45,1.75) 2(-2.45,1.25) 3(-2.45,0.75) 4(-2.45,0.25) 5(-2.45,-0.25) 6(-2.45,-0.75) 7(-2.45,-1.25) 8(-2.45,-1.75) 17(2.45,-1.75) 18(2.45,-1.25) 19(2.45,-0.75) 20(2.45,-0.25) 21(2.45,0.25) 22(2.45,0.75) 23(2.45,1.25) 24(2.45,1.75)
  oval 0.305x0.813 smd: 9(-1.75,-2.45) 10(-1.25,-2.45) 11(-0.75,-2.45) 12(-0.25,-2.45) 13(0.25,-2.45) 14(0.75,-2.45) 15(1.25,-2.45) 16(1.75,-2.45) 25(1.75,2.45) 26(1.25,2.45) 27(0.75,2.45) 28(0.25,2.45) 29(-0.25,2.45) 30(-0.75,2.45) 31(-1.25,2.45) 32(-1.75,2.45)
  rect 3.607x3.607 smd: 33(0,0)
QFN32_MC1320X
  oval 0.762x0.279 smd: 1(-2.32,1.751) 2(-2.32,1.251) 3(-2.32,0.751) 4(-2.32,0.25) 5(-2.32,-0.25) 6(-2.32,-0.751) 7(-2.32,-1.251) 8(-2.32,-1.751) 17(2.32,-1.751) 18(2.32,-1.251) 19(2.32,-0.751) 20(2.32,-0.25) 21(2.32,0.25) 22(2.32,0.751) 23(2.32,1.251) 24(2.32,1.751)
  oval 0.279x0.762 smd: 9(-1.751,-2.32) 10(-1.251,-2.32) 11(-0.751,-2.32) 12(-0.25,-2.32) 13(0.25,-2.32) 14(0.751,-2.32) 15(1.251,-2.32) 16(1.751,-2.32) 25(1.751,2.32) 26(1.251,2.32) 27(0.751,2.32) 28(0.25,2.32) 29(-0.25,2.32) 30(-0.751,2.32) 31(-1.251,2.32) 32(-1.751,2.32)
  custom 0.738x0.738 smd: 33(0,0)
QFN40_0P4_5X5MM
  oval 0.813x0.203 smd: 1(-2.46,1.8) 10(-2.46,-1.8) 21(2.46,-1.8) 30(2.46,1.8)
  rect 0.813x0.203 smd: 2(-2.46,1.4) 3(-2.46,1) 4(-2.46,0.6) 5(-2.46,0.2) 6(-2.46,-0.2) 7(-2.46,-0.6) 8(-2.46,-1) 9(-2.46,-1.4) 22(2.46,-1.4) 23(2.46,-1) 24(2.46,-0.6) 25(2.46,-0.2) 26(2.46,0.2) 27(2.46,0.6) 28(2.46,1) 29(2.46,1.4)
  oval 0.203x0.813 smd: 11(-1.8,-2.46) 20(1.8,-2.46) 31(1.8,2.46) 40(-1.8,2.46)
  rect 0.203x0.813 smd: 12(-1.4,-2.46) 13(-1,-2.46) 14(-0.6,-2.46) 15(-0.2,-2.46) 16(0.2,-2.46) 17(0.6,-2.46) 18(1,-2.46) 19(1.4,-2.46) 32(1.4,2.46) 33(1,2.46) 34(0.6,2.46) 35(0.2,2.46) 36(-0.2,2.46) 37(-0.6,2.46) 38(-1,2.46) 39(-1.4,2.46)
  rect 3.607x3.607 smd: 41(0,0)
RC0402_25
  round 0.635 smd: 1(-0.508,0) 2(0.508,0)
RC0603_OV
  oval 0.889x1.143 smd: 1(-0.762,0) 2(0.762,0)
RC0805_OV
  oval 0.889x1.524 smd: 1(-0.965,0) 2(0.965,0)
SC70-5
  rect 0.406x0.813 smd: 1(-0.65,-1.079) 2(0,-1.079) 3(0.65,-1.079) 4(0.65,1.079) 5(-0.65,1.079)
SC70-6
  rect 0.381x1.016 smd: 1(-0.65,-1.105) 2(0,-1.105) 3(0.65,-1.105) 4(0.65,1.105) 5(0,1.105) 6(-0.65,1.105)
SC-70
  rect 0.381x0.813 smd: 1(-0.66,-1.079) 2(0,-1.079) 3(0.66,-1.079) 4(0.66,1.079) 5(-0.66,1.079)
SC_75
  rect 0.483x0.635 smd: 1(-0.5,-0.647) 2(0.5,-0.647) 3(0,0.647)
SLP1616P6
  rect 0.305x0.635 smd: 1(-0.5,-0.76) 2(0,-0.76) 3(0.5,-0.76) 4(0.5,0.76) 5(0,0.76) 6(-0.5,0.76)
  rect 1.295x0.457 smd: 7(0,0)
SO8-25X75-200
  oval 0.635x1.905 smd: 1(-1.905,-3.67) 2(-0.635,-3.67) 3(0.635,-3.67) 4(1.905,-3.67) 5(1.905,3.67) 6(0.635,3.67) 7(-0.635,3.67) 8(-1.905,3.67)
SO8_1P27_4X5
  rect 1.6x0.61 smd: 1(-2.7,1.905) 2(-2.7,0.635) 3(-2.7,-0.635) 4(-2.7,-1.905) 5(2.7,-1.905) 6(2.7,-0.635) 7(2.7,0.635) 8(2.7,1.905)
SOD523
  rect 0.61x0.813 smd: A(0.85,0) C(-0.85,0)
SOD-123
  rect 1.321x1.219 smd: A(-1.626,0) C(1.626,0)
SOD_523_1P4
  rect 0.406x0.406 smd: A(0.7,0) C(-0.7,0)
SOIC8_1P27_7P6X5P95MM
  rect 1.803x0.61 smd: 1(-5.45,1.905) 2(-5.45,0.635) 3(-5.45,-0.635) 4(-5.45,-1.905) 5(5.45,-1.905) 6(5.45,-0.635) 7(5.45,0.635) 8(5.45,1.905)
SOT23
  rect 0.762x1.219 smd: 1(-1.016,-1.092) 2(1.016,-1.092) 3(0,1.092)
SOT23-5_A
  rect 1.016x0.762 smd: 1(-1.3,0.95) 2(-1.3,0) 3(-1.3,-0.95) 4(1.3,-0.95) 5(1.3,0.95)
SOT23_A
  rect 0.787x0.889 smd: 1(-0.94,-1.003) 2(0.94,-1.003) 3(0,1.003)
SOT23_S6
  rect 1.27x0.635 smd: 1(-1.219,0.94) 2(-1.219,0) 3(-1.219,-0.94) 4(1.219,-0.94) 5(1.219,0) 6(1.219,0.94)
SOT89_123_A
  rect 0.711x1.803 smd: 1(-1.5,-2.15) 3(1.5,-2.15)
  custom 0.5x0.5 smd: 2(0,-0.4)
SOT143B
  rect 0.991x0.61 smd: 1(-0.75,-1)
  rect 0.508x0.61 smd: 2(0.95,-1) 3(0.95,1) 4(-0.95,1)
SOT223
  rect 1.194x2.21 smd: 1(-2.3,-3.1) 2(0,-3.1) 3(2.3,-3.1)
  rect 3.734x2.21 smd: 4(0,3.1)
SOT323_3
  rect 0.406x0.991 smd: 1(0.65,-1.06) 2(-0.65,-1.06) 3(0,1.06)
SOT-23
  rect 1.016x1.397 smd: 1(-0.95,-1.1) 2(0.95,-1.1) 3(0,1.1)
SOT-363_0P65_SMT
  rect 0.762x0.381 smd: 1(-1.085,0.65) 2(-1.085,0) 3(-1.085,-0.65) 4(1.085,-0.65) 5(1.085,0) 6(1.085,0.65)
SOT-563_6P_0P5_SMT
  rect 0.61x0.279 smd: 1(-0.9,0.5) 2(-0.9,0) 3(-0.9,-0.5) 4(0.9,-0.5) 5(0.9,0) 6(0.9,0.5)
SOT_143
  rect 1.219x1.397 smd: 1(-0.75,-1.1)
  rect 1.016x1.397 smd: 2(0.95,-1.1) 3(0.95,1.1) 4(-0.95,1.1)
SPACER_139T
  round 5.588 hole 3.531: 1(0,0)
SSOP8
  rect 1.27x0.432 smd: 1(-1.85,0.975) 2(-1.85,0.325) 3(-1.85,-0.325) 4(-1.85,-0.975) 5(1.85,-0.975) 6(1.85,-0.325) 7(1.85,0.325) 8(1.85,0.975)
SSOP8_DCU
  rect 0.279x1.219 smd: 1(-0.75,-1.499) 2(-0.25,-1.499) 3(0.25,-1.499) 4(0.75,-1.499) 5(0.75,1.499) 6(0.25,1.499) 7(-0.25,1.499) 8(-0.75,1.499)
SW2_SPST_4X3_SM_F
  rect 0.965x1.397 smd: 1(-2.075,0) 2(2.075,0)
SW4_DIP_1P27_6P3X5P7
  rect 0.762x1.27 smd: 1(-1.905,-3.81) 2(-0.635,-3.81) 3(0.635,-3.81) 4(1.905,-3.81) 5(1.905,3.81) 6(0.635,3.81) 7(-0.635,3.81) 8(-1.905,3.81)
SW4_PB_6P2SQ_SM
  rect 1.549x1.295 smd: 1(-3.975,2.25) 2(-3.975,-2.25) 3(3.975,2.25) 4(3.975,-2.25)
SW6_DPDT_11X6MM
  rect 1.143x1.143 hole 0.711: 1(0,0)
  round 1.143 hole 0.711: 2(2,0) 3(4,0) 4(0,-2.5) 5(2,-2.5) 6(4,-2.5)
TESTPOINT_35MIL
  round 0.889 smd: 1(0,0)
TP_TH_018
  round 0.914 hole 0.457: 1(0,0)
TP_TH_063
  round 2.311 hole 1.6: 1(0,0)
TPAD_020
  round 0.508 smd: 1(0,0)
TPAD_030
  round 0.762 smd: 1(0,0)
TPAD_050
  round 1.27 smd: 1(0,0)
TSOPII_54
  rect 2.134x0.559 smd: 1(-5.793,10.4) 2(-5.793,9.6) 3(-5.793,8.8) 4(-5.793,8) 5(-5.793,7.2) 6(-5.793,6.4) 7(-5.793,5.6) 8(-5.793,4.8) 9(-5.793,4) 10(-5.793,3.2) 11(-5.793,2.4) 12(-5.793,1.6) 13(-5.793,0.8) 14(-5.793,0) 15(-5.793,-0.8) 16(-5.793,-1.6) 17(-5.793,-2.4) 18(-5.793,-3.2) 19(-5.793,-4) 20(-5.793,-4.8) 21(-5.793,-5.6) 22(-5.793,-6.4) 23(-5.793,-7.2) 24(-5.793,-8) 25(-5.793,-8.8) 26(-5.793,-9.6) 27(-5.793,-10.4) 28(5.793,-10.4) 29(5.793,-9.6) 30(5.793,-8.8) 31(5.793,-8) 32(5.793,-7.2) 33(5.793,-6.4) 34(5.793,-5.6) 35(5.793,-4.8) 36(5.793,-4) 37(5.793,-3.2) 38(5.793,-2.4) 39(5.793,-1.6) 40(5.793,-0.8) 41(5.793,0) 42(5.793,0.8) 43(5.793,1.6) 44(5.793,2.4) 45(5.793,3.2) 46(5.793,4) 47(5.793,4.8) 48(5.793,5.6) 49(5.793,6.4) 50(5.793,7.2) 51(5.793,8) 52(5.793,8.8) 53(5.793,9.6) 54(5.793,10.4)
TSOT23_8_0P65_2X1
  rect 1.219x0.432 smd: 1(-1.31,0.975) 2(-1.31,0.325) 3(-1.31,-0.325) 4(-1.31,-0.975) 5(1.31,-0.975) 6(1.31,-0.325) 7(1.31,0.325) 8(1.31,0.975)
TSSOP8
  rect 1.778x0.356 smd: 1(-2.819,0.975) 2(-2.819,0.325) 3(-2.819,-0.325) 4(-2.819,-0.975) 5(2.819,-0.975) 6(2.819,-0.325) 7(2.819,0.325) 8(2.819,0.975)
TSSOP8_A
  rect 1.448x0.457 smd: 1(-2.15,0.975) 2(-2.15,0.325) 3(-2.15,-0.325) 4(-2.15,-0.975) 5(2.15,-0.975) 6(2.15,-0.325) 7(2.15,0.325) 8(2.15,0.975)
TSSOP14
  rect 1.524x0.457 smd: 1(-2.959,1.951) 2(-2.959,1.3) 3(-2.959,0.65) 4(-2.959,0) 5(-2.959,-0.65) 6(-2.959,-1.3) 7(-2.959,-1.951) 8(2.959,-1.951) 9(2.959,-1.3) 10(2.959,-0.65) 11(2.959,0) 12(2.959,0.65) 13(2.959,1.3) 14(2.959,1.951)
TSSOP24_65MM
  rect 1.524x0.305 smd: 1(-2.92,3.58) 2(-2.92,2.93) 3(-2.92,2.28) 4(-2.92,1.63) 5(-2.92,0.98) 6(-2.92,0.33) 7(-2.92,-0.32) 8(-2.92,-0.97) 9(-2.92,-1.62) 10(-2.92,-2.27) 11(-2.92,-2.92) 12(-2.92,-3.57) 13(2.92,-3.57) 14(2.92,-2.92) 15(2.92,-2.27) 16(2.92,-1.62) 17(2.92,-0.97) 18(2.92,-0.32) 19(2.92,0.33) 20(2.92,0.98) 21(2.92,1.63) 22(2.92,2.28) 23(2.92,2.93) 24(2.92,3.58)
unnamed#2
  round 1.524 smd: (0,0)
UQFN10_0P5_2P05X1P55
  rect 0.66x0.305 smd: 1(-0.705,0.75) 4(-0.705,-0.75) 6(0.705,-0.75) 9(0.705,0.75)
  rect 0.66x0.254 smd: 2(-0.705,0.25) 3(-0.705,-0.25) 7(0.705,-0.25) 8(0.705,0.25)
  rect 0.356x0.66 smd: 5(0,-0.905) 10(0,0.905)
WLCSP12_0P4_1P38X1P68MM_SMDP
  round 0.254 smd: A1(-0.4,0.6) A2(0,0.6) A3(0.4,0.6) B1(-0.4,0.2) B2(0,0.2) B3(0.4,0.2) C1(-0.4,-0.2) C2(0,-0.2) C3(0.4,-0.2) D1(-0.4,-0.6) D2(0,-0.6) D3(0.4,-0.6)
XFMR6_6P6X6P2
  rect 1.194x1.295 smd: (-2.73,0) (2.73,0) 1(-2.73,2.54) 3(-2.73,-2.54) 4(2.73,-2.54) 6(2.73,2.54)
XSON10_0P5_1P1X2P6MM
  rect 0.711x0.254 smd: 1(-0.457,1) 2(-0.457,0.5) 3(-0.457,0) 4(-0.457,-0.5) 5(-0.457,-1) 6(0.457,-1) 7(0.457,-0.5) 8(0.457,0) 9(0.457,0.5) 10(0.457,1)
XTAL2-3P2X1P5-SM
  rect 1.092x1.905 smd: 1(-1.25,0) 2(1.25,0)
XTAL4_5P2X3P4MM_SM
  rect 1.6x1.27 smd: 1(-1.85,-1.1) 2(1.85,-1.1) 3(1.85,1.1) 4(-1.85,1.1)
XTL4_2P1X1P7MM_SM
  rect 0.762x0.711 smd: 1(-0.675,-0.5) 2(0.675,-0.5) 3(0.675,0.5) 4(-0.675,0.5)
XTLOSC4_2P6X2P1MM_SM
  rect 1.194x1.016 smd: 1(-0.85,-0.66) 2(0.85,-0.66) 3(0.85,0.66) 4(-0.85,0.66)
XTLOSC4_3P3X1P6_SM
  rect 0.991x0.813 smd: 1(-1.35,-0.6) 2(1.35,-0.6) 3(1.35,0.6) 4(-1.35,0.6)

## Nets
5V_SDA_PSW: C365.1 D43.A U52.C2 U52.D1 U52.D2
5V_SYS: C17.1 C18.1 C25.1 C26.1 C300.1 C301.1 C579.1 C580.1 D27.A J1.2 J1.4 J1.6 J1.8(B4) J45.16(B8) J47.10 J47.12 J70.7 L22.2 R7.1 R12.1 R622.1 R633.1 R644.1 R653.1 R2584.1 U3.1 U3.3(S\H\D\N\) U5.1 U369.A2 U369.C2
5V_USB_OTG1: C87.1 C361.1 C364.1 D41.A L15.2 U6.D17 U37.C2 U37.D1 U37.D2
5V_USB_OTG2: C89.1 C362.1 C363.1 D42.A L18.2 U6.D16 U39.C2 U39.D1 U39.D2
GND: BH1.1 BH12.1 C1.2 C2.2 C3.2 C5.2 C6.2 C7.2 C8.2 C9.2 C10.2 C11.2 C12.2 C13.2 C14.2 C17.2 C18.2 C19.2 C20.2 C21.2 C22.2 C23.2 C24.2 C25.2 C26.2 C27.2 C28.2 C29.2 C30.2 C31.2 C32.2 C33.2 C34.2 C35.2 C36.2 C37.2 C38.2 C39.2 C42.2 C43.2 C44.2 C45.2 C46.2 C47.2 C48.2 C49.2 C51.2 C53.2 C54.2 C55.2 C56.2 C57.2 C58.2 C59.2 C60.2 C61.2 C62.2 C63.2 C64.2 C65.2 C66.2 C68.2 C69.2 C70.2 C71.2 C72.2 C73.2 C74.2 C75.2 C76.2 C77.2 C78.2 C79.2 C80.2 C81.2 C82.2 C83.2 C84.2 C85.2 C86.2 C87.2 C88.2 C89.2 C90.2 C91.2 C92.2 C93.2 C94.2 C95.2 C96.2 C98.2 C99.2 C100.2 C101.2 C102.2 C103.2 C104.2 C105.2 C106.2 C107.2 C108.2 C109.2 C110.2 C111.2 C112.2 C113.2 C114.2 C115.2 C116.2 C117.2 C118.2 C119.2 C120.2 C121.2 C122.2 C123.2 C124.2 C125.2 C126.2 C167.2 C168.2 C170.2 C176.2 C177.2 C178.2 C179.2 C180.2 C181.1 C182.2 C183.2 C184.2 C185.2 C186.1 C187.2 C188.2 C189.2 C190.2 C191.2 C192.2 C193.2 C194.2 C195.2 C196.2 C197.2 C198.2 C199.2 C200.2 C201.2 C202.2 C203.2 C204.2 C205.2 C206.2 C207.2 C208.1 C209.2 C210.2 C211.2 C212.2 C213.2 C214.2 C215.2 C216.2 C217.2 C218.2 C219.2 C220.2 C221.2 C222.2 C223.2 C224.2 C225.2 C226.2 C227.2 C228.2 C229.2 C230.1 C231.2 C232.2 C233.2 C234.2 C235.2 C236.2 C237.2 C238.2 C239.2 C240.2 C241.2 C242.2 C243.2 C244.2 C245.2 C246.2 C247.2 C248.2 C263.2 C264.2 C267.2 C268.2 C270.2 C271.2 C272.2 C273.1 C274.2 C275.2 C276.2 C277.2 C278.2 C279.1 C280.2 C281.2 C282.2 C283.2 C284.2 C285.2 C286.2 C287.2 C288.2 C289.2 C290.2 C291.2 C292.2 C293.2 C294.2 C295.2 C296.2 C297.2 C298.2 C299.2 C300.2 C301.2 C304.2 C305.2 C308.2 C309.2 C310.2 C311.2 C312.2 C317.2 C323.2 C324.2 C326.2 C338.2 C346.2 C347.2 C348.2 C349.2 C350.2 C351.2 C352.2 C353.2 C354.2 C355.2 C356.2 C358.2 C359.2 C360.2 C361.2 C362.2 C363.2 C364.2 C365.2 C370.2 C371.2 C372.2 C373.2 C385.2 C386.2 C387.2 C388.2 C389.2 C390.2 C391.2 C392.2 C393.2 C394.2 C395.2 C397.2 C398.2 C399.2 C401.2 C402.2 C403.2 C404.2 C405.2 C406.2 C407.2 C408.2 C409.2 C410.2 C411.2 C412.2 C413.2 C414.2 C431.2 C432.2 C433.2 C434.2 C435.2 C436.2 C452.2 C455.2 C462.2 C463.2 C464.2 C465.2 C466.2 C468.2 C469.2 C470.2 C471.2 C472.2 C473.2 C475.2 C476.2 C477.2 C478.2 C479.2 C480.2 C481.2 C482.2 C507.2 C508.2 C509.1 C510.2 C511.2 C512.2 C513.2 C514.2 C515.2 C516.2 C517.2 C518.2 C519.2 C520.2 C521.2 C522.2 C523.2 C524.2 C525.2 C526.2 C527.2 C528.2 C529.2 C530.2 C562.2 C563.2 C565.2 C567.2 C569.2 C571.2 C573.2 C574.2 C575.2 C576.2 C577.2 C578.2 C579.2 C580.2 C581.2 C582.2 C583.2 C584.2 C585.2 C586.2 C588.2 C589.2 C590.2 C591.2 C593.2 C594.1 C595.1 C598.2 C599.2 C602.2 C603.2 C604.2 C887.2 C902.2 C903.2 C908.2 C909.2 C910.2 D1.A D3.4(CATHODE2) D10.A D11.A D12.A D13.A D14.A D15.A D16.A D17.A D18.A D19.A D20.A D21.3 D22.3 D46.2(A2) H1.1(NC_1) H2.1(NC_1) H3.1(NC_1) H4.1(NC_1) H5.1(NC_1) H6.1(NC_1) J2.2 J2.3 J7.2 J8.2 J15.6(VSS) J15.SH1 J15.SH2 J15.SH3 J15.SH4 J29.10 J30.10 J31.10 J33.5 J34.2 J35.2 J36.1 J36.7 J36.18 J36.33 J36.39 J36.45 J36.51 J36.57 J36.63 J36.69 J36.75 J37.4 J37.6 J37.8 J37.10 J37.12 J37.14 J37.16 J37.18 J37.20 J41.1 J41.3 J44.11 J44.13 J44.14 J44.15 J44.17 J44.19 J45.12 J45.14 J47.2 J47.6 J47.14 J47.24 J48.2 J48.4 J48.6 J50.4 J51.7 J51.8(B4) J53.5 J56.3 J56.5 J57.3 J58.3 J59.3 J60.5 J62.8 J63.3 J65.3 J67.11 J67.12(B6) J68.5 J69.2 J70.8 J71.7 J71.8 J71.11 J71.12 J71.15 J71.16 J71.19 J71.20 J71.23 J71.24 J71.SH1 J71.SH2 J71.SH3 J71.SH4 J72.3 J73.3 J75.3 J76.3 J101.5 J134.2 J134.6 J134.11 J134.12 J134.17 J134.18 J134.21 J134.22 J134.25 J134.26 J134.29 J134.30 J134.33 J134.34 J134.39 J134.40 J134.45 J134.46 J134.53 J134.SH1 J134.SH2 J134.SH3 J134.SH4 JP2.1 JP3.1 JP4.1 JP5.1 L25.1 Q1.3 Q4.2(SOURCE) Q7.2(EMITTER) Q8.2(EMITTER) Q11.1(SOURCE) Q12.1(SOURCE) Q15.2(SOURCE) Q19.2(EMITTER) Q20.2(EMITTER) Q21.2(EMITTER) Q23.2(EMITTER) R11.2 R16.2 R19.2 R23.2 R27.2 R28.2 R30.2 R38.2 R39.2 R55.2 R57.2 R259.2 R260.2 R331.2 R338.2 R341.1 R377.2 R378.2 R382.2 R404.1 R432.2 R437.2 R438.2 R439.2 R440.2 R441.2 R442.2 R443.2 R445.2 R449.2 R452.2 R454.1 R467.2 R492.2 R493.2 R494.2 R495.2 R496.2 R497.2 R498.2 R499.2 R500.2 R505.2 R506.2 R507.1 R520.2 R528.2 R543.2 R544.2 R545.2 R547.2 R548.2 R549.2 R550.2 R552.2 R558.2 R559.2 R560.1 R573.2 R626.2 R631.2 R638.2 R642.2 R648.2 R657.2 R707.1 R709.1 R711.1 R719.2 R720.2 R721.2 R738.2 R761.2 R765.2 R770.2 R779.2 R780.1 R781.1 R803.2 R804.1 R805.2 R806.2 R811.2 R815.2 R817.2 R821.2 R823.2 R824.2 R825.2 R826.2 R827.2 R828.2 R836.2 R837.2 R839.2 R876.2 R879.2 R886.2 R892.2 R1031.2 R1034.2 R1035.2 R1043.2 R1046.1 R1048.2 R1097.1 R1099.1 R1103.2 R1104.2 R1106.2 R1109.2 R1112.2 R1116.2 R1118.1 R1171.2 R1173.2 R1175.2 R1177.2 R1178.2 R1181.2 R1192.1 R1280.1 R1286.1 R1325.2 R1326.2 R1327.2 R2137.2 R2146.2 R2147.2 R2148.2 R2149.2 R2150.2 R2151.2 R2156.1 SW1.3 SW1.6(NO2) SW2.1 SW2.3 SW3.1 SW3.3 SW6.2(SW2) SW7.1 SW7.3 SW8.1 SW8.3 T1.4 TP3.1 TP4.1 TP5.1 TP6.1 TP103.1(PIN1) TVS1.1 U1.4 U1.6 U2.1 U3.2 U4.1 U5.2 U6.A1 U6.A17 U6.C11 U6.C14 U6.D4 U6.D7 U6.D8 U6.D12 U6.F11 U6.F12 U6.F13 U6.G4 U6.G7 U6.G8 U6.G9 U6.G10 U6.G11 U6.G14 U6.H7 U6.H11 U6.J7 U6.J11 U6.K6 U6.K7 U6.K8 U6.K9 U6.K11 U6.L4 U6.L10 U6.L11 U6.L14 U6.P3 U6.P4 U6.P7 U6.P14 U6.T11 U6.T12 U6.U1 U6.U17 U10.4 U11.B3 U11.C1 U11.E5(VSS3) U12.4 U13.4 U14.6 U14.12 U14.28 U14.41 U14.46 U14.52 U14.54 U15.B3 U15.C1 U15.E5(VSSQ2) U16.6 U16.12 U16.28 U16.41 U16.46 U16.52 U16.54 U22.2 U23.3 U25.2 U26.3 U26.8 U27.41 U28.3 U28.8 U29.41 U30.3 U30.8 U31.3 U31.8 U32.3 U32.8 U33.3 U33.8 U34.41 U37.B3 U37.C3 U37.D3 U38.7 U39.B3 U39.C3 U39.D3 U40.7 U41.2 U42.2 U43.11 U43.12 U43.13 U43.22 U44.11 U44.12 U44.13 U44.22 U45.5 U46.6 U46.7 U48.2 U48.3 U48.4 U51.1 U52.B3 U52.C3 U52.D3 U55.B1 U55.B5 U55.B9 U55.B13 U55.H1 U55.H2 U55.J13 U55.M11 U55.M12 U55.N1 U55.N5 U55.N12 U56.2 U56.5 U57.2 U58.4 U59.2 U60.6 U61.2 U61.8 U61.10 U61.17 U62.1 U63.5 U64.5 U65.5 U66.5 U67.5 U68.5 U69.5 U70.5 U71.5 U72.4 U72.17 U72.20 U72.24 U72.26 U72.33 U73.4 U74.7 U96.5 U97.5 U98.5 U99.5 U100.5 U101.5 U103.5 U106.5 U115.10 U116.3 U117.3 U118.3 U119.3 U121.33 U123.33 U124.2 U125.2 U126.2 U312.1 U356.1 U361.7 U362.3 U365.3 U366.3 U369.B1 U369.C1 U369.C7 U369.D7 U369.F2 U369.F3 U369.G5 U410.3 U416.3 U417.3 U418.3 X1.2 X1.4 X2.2 X2.4 X3.2 X3.4 X4.2 X4.4 X6.2 X6.4 Y2.2 Y2.4 Y3.2 Y4.2 Y4.4
GND_RJ45_SHELL0: C181.2 J28.15 J28.16 R404.2
GND_RJ45_SHELL1: C186.2 J29.SH1 J29.SH2 R454.2
GND_RJ45_SHELL2: C208.2 J30.SH1 J30.SH2 R507.2
GND_RJ45_SHELL3: C230.2 J31.SH1 J31.SH2 R560.2
GND_RJ45_SHELL4: C509.2 J32.15 J32.16 R1192.2
P3V3_SDA: C346.1 C347.1 C348.1 C349.1 C353.1 C354.1 C358.1 C371.1 C373.1 C385.1 C386.1 C388.1 C390.1 C398.1 C574.1 C575.1 C576.1 R808.1 R814.1 R829.2 R830.2 R844.1 R845.1 R851.1 R853.1 R854.1 R861.2 R862.2 R863.2 R864.2 R865.2 R866.2 R1088.1 R2107.1 R2109.1 R2111.1 U55.A3 U55.A5 U55.A9 U55.A13 U55.M1 U55.M13 U55.N7 U55.N13 U56.1 U57.1 U58.1 U59.1 U61.16(VCCB) U62.3(VOUT) U362.5 U365.5 U366.5
P5V_SDA: C338.1 C359.1 C360.1 C370.1 C372.1 L24.2 R816.1 R850.1 U52.B1 U52.B2 U52.C1(VINT3) U62.2
VCC_I3C: C310.1 C311.1 R771.2 R772.1 R773.2 R774.1 R775.1 R776.1 R777.1 U46.5(VDDIO)
VDD_1V8: C79.1 C290.1 C291.1 C298.1 C299.1 C524.1 C563.1 C903.1 J4.1 J10.2 J11.1 J47.8 L2.1 L7.1 R457.2 R692.1 R694.1 R706.1 R1320.1 R2090.1 R2102.1 R2135.1 R2684.1 R2694.1 U6.D11 U6.E11 U43.23 U43.24(VCCB2) U44.1 U126.3 U361.14 U410.5
VDD_AON_3V3: J9.1 R51.2 R52.1
VDD_AON_ANA: C42.1 J11.3 U6.P12
VDD_AON_DIG: C47.1 U6.P11
VDD_AON_IN: C43.1 J9.2 R52.2 U6.U14
VDD_BBSM_3V3: C14.1 D8.A R34.1 R40.2 R43.2 R2098.1 U2.4(VCC)
VDD_BBSM_ANA: C35.1 R47.2 U6.R12
VDD_BBSM_IN: C34.1 J6.2 R41.2 U6.U12
VDD_COIN_3V: D9.A J7.1 R45.1
VDD_SOC_IN: C51.1 C53.1 C54.1 C55.1 C56.1 C59.1 J14.1 R59.1 R2161.2 U6.H8 U6.H9 U6.H10 U6.J8 U6.J9 U6.J10 U6.K10
VDD_USB_1P8: C85.1 L6.2 L7.2 U6.B17
VDD_USB_3P3: C86.1 L8.2 U6.G12(VDD_USB_3P3)
VDD_VREFH: C46.1 J10.1 U6.H16
VDDA_1P0: C57.1 U6.N11
VDDA_ADC_3P3: C529.1 L3.2 R1340.2 U312.3
ADC_1V8_IN: C48.1 C49.1 C58.1 L4.2 R1339.1 U6.J13 U6.M12
AUD_INT: R2145.2 R2153.2
BOOT_MODE[0]: J102.2 R707.2 R708.1 SW5.4
BOOT_MODE[1]: J103.2 R709.2 R710.1 SW5.3
BOOT_MODE[2]: J104.2 R711.2 R712.1 SW5.2
BT_DEV_WAKE: R1081.2 U43.9
BT_DEV_WAKE_1V8: J36.42 R2168.2 U43.15
BT_LED2_B: D24.C(CATHODE) J36.16
BT_PCM_BCLK: J80.2 R1090.2 U43.7
BT_PCM_BCLK_1V8: J78.2 R683.1 R701.1
BT_PCM_RXD: R699.2 U6.K13
BT_PCM_RXD_1V8: R685.1 U44.6
BT_PCM_SYNC: J81.2 U6.K14 U43.8
BT_PCM_SYNC_1V8: J79.2 R684.1 R703.1
BT_PCM_TXD: R1089.2 U43.6
BT_PCM_TXD_1V8: R687.1 U43.18
BT_RST#: R141.2 R669.1
BT_UART10_CTS: R148.2 R697.2
BT_UART10_RTS: R149.2 U43.5
BT_UART10_RXD: R146.2 R696.2
BT_UART10_TXD: R144.2 U43.4
BT_UART_CTS_1V8: R681.1 U44.5
BT_UART_RTS_1V8: R682.1 U43.19
BT_UART_RXD_1V8: R678.1 U44.4
BT_UART_TXD_1V8: R680.1 U43.20
BT_WAKE_B_3V3: R143.2 R677.1
CAN1_H: C273.2 D21.2(CATHODE2) FL1.1 J34.1 R649.2 R650.1
CAN1_L: C275.1 D21.1 FL1.2 J34.3 R651.2 R652.2
CAN1_RX: R1343.2 U41.4
CAN1_TX: R1342.2 U41.1
CAN3_H: C279.2 D22.2(CATHODE2) FL2.1 J35.1 R658.2 R659.1
CAN3_L: C281.1 D22.1 FL2.2 J35.3 R660.2 R661.2
CAN3_RX: U6.C8 U42.4
CAN3_TX: R1344.2 U42.1
CAN_STBY: R647.1 R656.1 U6.L15
CCM_CLKO1_25M: R1330.2 R1332.1 R1334.1
CCM_ENET_REF_CLK_25M: R1328.2 R1331.1 R1333.1
CODEC_1V8: C583.1 C584.1 C585.1 C586.1 R2135.2 U369.C6 U369.D6 U369.G2 U369.G4
COEX1: J36.48 J108.3
COEX2: J36.46 J108.4
COEX3: J36.44 J108.5
CONN_ENET_MDC: J134.50 R2593.1
CONN_ENET_MDIO: J134.48 R2592.1
CONN_ENET_RD0: J134.36 R276.1
CONN_ENET_RD1: J134.38 R277.1
CONN_ENET_RD2: J134.42 R2618.1
CONN_ENET_RD3: J134.44 R2619.1
CONN_ENET_RX_CTL: J134.28 R274.1
CONN_ENET_RXC: J134.32 R275.1
CONN_ENET_TD0: J134.16 R271.1
CONN_ENET_TD1: J134.14 R2576.1
CONN_ENET_TD2: J134.10 R2617.1
CONN_ENET_TD3: J134.8 R2616.1
CONN_ENET_TX_CTL: J134.24 R273.1
CONN_ENET_TXC: J134.20 R272.1
CPCA: C587.1 U369.B6
CPCB: C587.2 U369.B7
CPVOUTN: C591.1 U369.A7
CPVOUTP: C590.1 U369.A6
DBG_OUT_3V3: C411.1 U72.16
DBG_RXLED: D37.1 R899.2
DBG_TXLED: D37.3 R898.2
DBGIF_DETECT: R840.1 U55.E9
DBGIF_ISP0_CTRL: R841.1 U55.C13
DBGIF_ISP1_CTRL: R2107.2 TP57.1(TP) U55.B8 U362.2
DBGIF_ISP2_CTRL: R2109.2 TP58.1(TP) U55.E13 U365.2
DBGIF_ISP3_CTRL: R2111.2 TP59.1(TP) U55.G8 U366.2
DBGIF_ISP4_CTRL: R822.2 TP60.1(TP) U55.G11
DBGIF_RESET: U55.E6 U57.3
DBGIF_RESET_TXEN: R837.1 U55.C12 U57.5
DBGIF_TCK_SWCLK: U55.L12 U58.2
DBGIF_TDI: U55.F5 U58.3
DBGIF_TDO_SWO: U55.F8 U56.3
DBGIF_TMS_SWDIO: U55.B11 U59.3
DBGIF_TMS_SWDIO_TXEN: R836.1 U55.F13 U59.5
DBGIF_VREF: C392.1 R838.2 R839.1 U55.L1
DBUG_5V: C412.1 C413.1 C414.1 L29.1 R898.1 R899.1 R900.1 U72.1(VCCIO) U72.19
DBUG_RST: R900.2 U72.18
DBUG_USB_DM: J60.2 U72.15 U74.1
DBUG_USB_DP: J60.3 U72.14 U74.2
DC_5V_IN: C3.1 F1.1 J2.1 R6.1
DC_GPIO1: J47.21 R1083.2
DC_GPIO2: J47.22 R1086.2
DC_I2S1_MCLK: J47.1 R95.2
DC_I2S1_RX_BCLK: J47.5 R98.2
DC_I2S1_RX_D0: J47.11 R96.2
DC_I2S1_RX_SYNC: J47.9 R99.2
DC_I2S1_TX_BCLK: J47.23 R94.2
DC_I2S1_TX_D0: J47.17 R92.2
DC_I2S1_TX_D1: J47.18(B9) R97.2
DC_I2S1_TX_SYNC: J47.16 R93.2
DC_I2S4_MCLK: J48.1 R125.2
DC_I2S4_RX_BCLK: J48.5 R133.2
DC_I2S4_RX_D0: J48.8 R134.2
DC_I2S4_RX_SYNC: J48.7 R132.2
DC_I2S4_TX_BCLK: J48.3 R127.2
DC_I2S4_TX_D0: J48.10(B5) R131.2
DC_I2S4_TX_SYNC: J48.9 R129.2
DC_INT: J47.3 R1085.2
DC_RESET: J47.7 R1084.2
DCDC_1V8_OUT: J77.2 L6.1 R58.2
DCDC_3V3: C8.1 C9.1 J3.2 L1.2 R14.1 TP1.1(TP) U1.5
DCDC_3V3_PG: C11.1 C12.1 TP2.1(TP) U1.1 U5.3(S\H\D\N\)
DMIC_CLK: R867.2 R1021.2 U116.4 U117.4 U118.4 U119.4
DMIC_DATA0: R343.2 R868.2 R1022.1
DMIC_DATA1: R100.2 R344.2 R1023.1
DMIC_DATA2: R101.2 R348.2 R1024.1
DMIC_DATA3: R102.2 R350.2 R1025.1
ECAT0_RST_B: R958.2 R1274.1
ECAT0_RX_DV: R1260.1 U101.4
ECAT0_RXCLK: R1259.1 U97.3
ECAT0_RXD0: R1262.1 U100.4
ECAT0_RXD1: R1263.1 U101.3
ECAT0_RXD2: R1264.1 U98.3
ECAT0_RXD3: R1265.1 U97.4
ECAT0_RXER: R960.2 R1261.1
ECAT0_TX_REF_CLK: R1266.1 U100.3
ECAT0_TXD0: R1268.1 U98.4
ECAT0_TXD1: R1269.1 U99.3
ECAT0_TXD2: R1270.1 U96.4
ECAT0_TXD3: R1272.1 U96.3
ECAT0_TXEN: R1267.1 U99.4
ECAT1_RST_B: R1018.2 R1312.1
ECAT1_RX_DV: R1298.1 R2120.2
ECAT1_RXCLK: R1297.1 R2132.2
ECAT1_RXD0: R1300.1 R2116.2
ECAT1_RXD1: R1302.1 R2117.2
ECAT1_RXD2: R1301.1 R2124.2
ECAT1_RXD3: R1303.1 R2125.2
ECAT1_RXER: R1299.1 R2121.2
ECAT1_TX_REF_CLK: R1304.1 U103.4
ECAT1_TXD0: R1307.1 U106.4
ECAT1_TXD1: R1306.1 U106.3
ECAT1_TXD2: R1308.1 R2129.2
ECAT1_TXD3: R1310.1 R2128.2
ECAT1_TXEN: R1305.1 U103.3
ECAT_ACT0: R883.2 R885.2 TP65.1(TP)
ECAT_ACT1: R884.2 R891.2 TP66.1(TP)
ECAT_LINK0: J28.14 R1116.1 R1117.2 R2159.2 U121.25
ECAT_LINK1: J32.14 R1172.2 R1173.1 R2160.2 U123.25
ECAT_SYNC0: R875.2 R881.2 TP63.1(TP)
ECAT_SYNC1: R878.2 R882.2 TP64.1(TP)
ENET0_CRS_DV: R234.2 R1122.1 R2606.1
ENET0_INT_B: R1236.1 U6.M13
ENET0_RST_B: R405.1 U6.M15
ENET0_RXD0: R232.2 R1233.1 R2604.1
ENET0_RXD1: R233.2 R1234.1 R2605.1
ENET0_RXER: R235.2 R1235.1 R2607.1
ENET0_TX_REF_CLK: R231.2 R1240.1 R2603.1
ENET0_TXD0: R228.2 R1237.1
ENET0_TXD1: R229.2 R1238.1
ENET0_TXEN: R230.2 R1239.1 R2620.1
ENET1_INT_B: R2643.2 R2694.2 U416.4(Y)
ENET1_RGMII_RX_EN: R463.2 U6.B10
ENET1_RGMII_RXC: C201.1 R462.2 U6.A12
ENET1_RGMII_RXD0: R458.2 U6.B13
ENET1_RGMII_RXD1: R460.2 U6.B12
ENET1_RGMII_RXD2: R459.2 U6.A15
ENET1_RGMII_RXD3: R461.2 U6.A13
